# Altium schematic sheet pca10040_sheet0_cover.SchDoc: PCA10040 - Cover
size A3; Revision: 1.1.0; SheetNumber: 0; SheetTotal: 5; DrawnBy: KJP; ProjectNumber: 4397; DocumentSize: A3; PCBRevision: 0071KJP; PCAName: PCA10040; PCBNumber: 400150
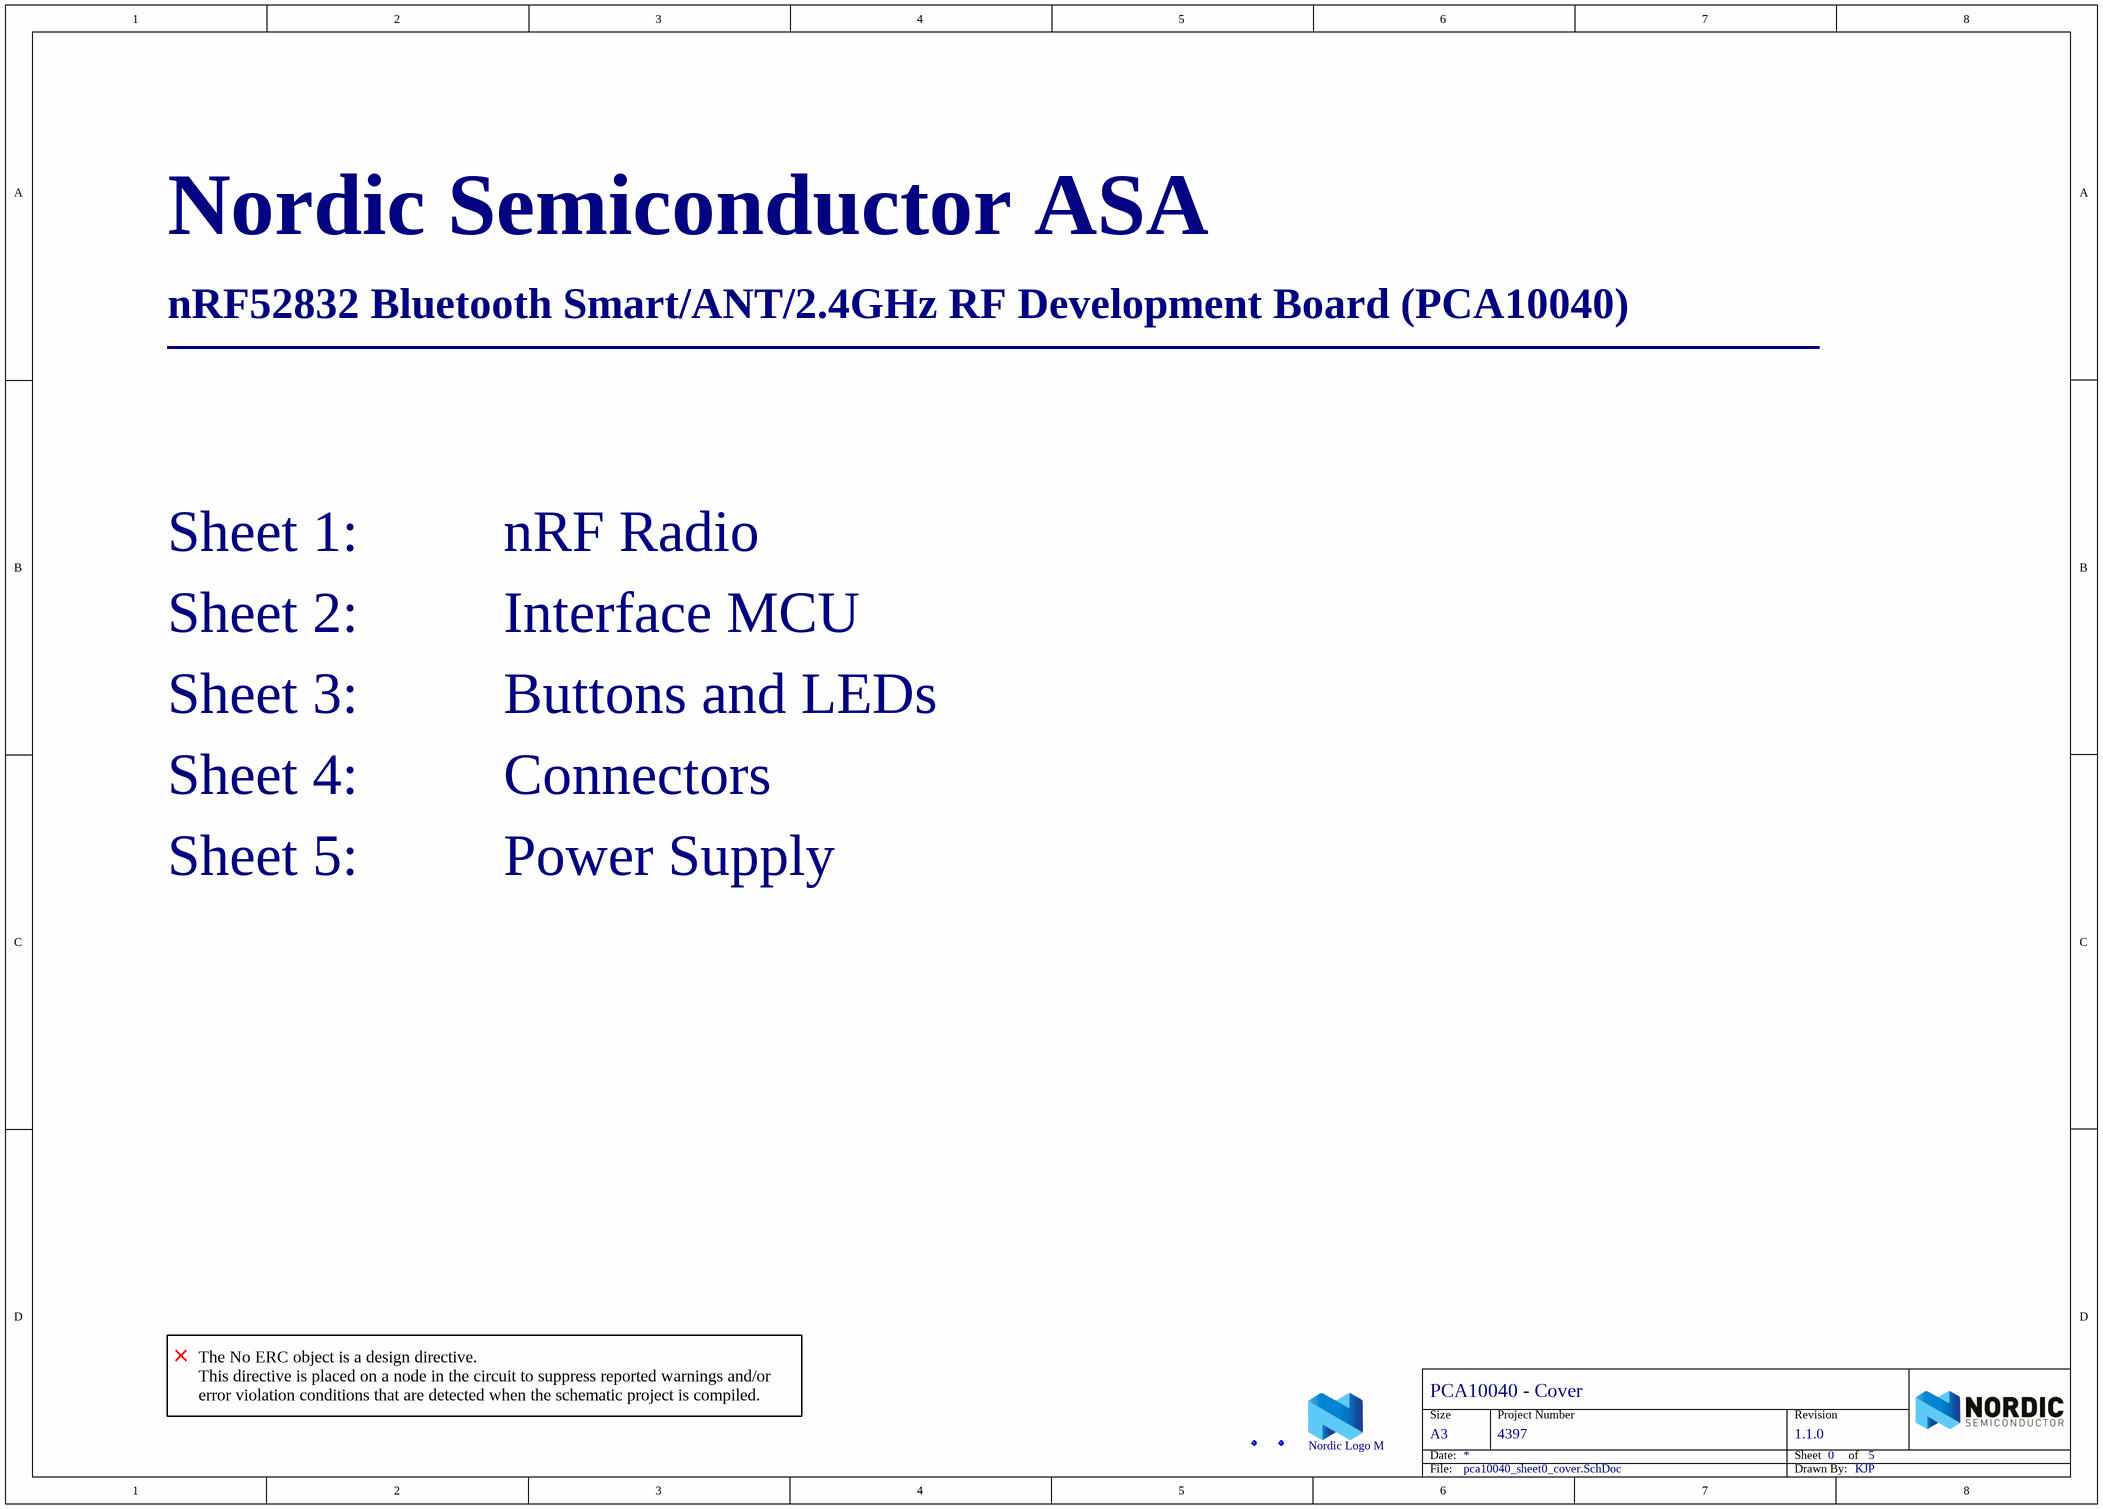
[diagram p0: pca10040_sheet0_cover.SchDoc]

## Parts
Fid1  Fiducial mark  [Fiducial]  (value not drawn)
Fid2  Fiducial mark  [Fiducial]  (value not drawn)
LOGO1  Nordic Logo M  [NORDIC_LOGO_M]  (no BOM)

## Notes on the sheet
- Nordic Semiconductor ASA
- nRF52832 Bluetooth Smart/ANT/2.4GHz RF Development Board (PCA10040)
- ________________________________________________________
- Sheet 1:          nRF Radio
- Sheet 2:          Interface MCU
- Sheet 3:          Buttons and LEDs
- Sheet 4:          Connectors
- Sheet 5:          Power Supply
- The No ERC object is a design directive.
  This directive is placed on a node in the circuit to suppress reported warnings and/or error violation conditions that are detected when the schematic project is compiled.

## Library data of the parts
Fid1 Fid2 = Fid-Mark: Artikkelnr Noca: N.A.
LOGO1 = Nordic Logo M: Nordic Logo, medium size; Artikkelnr Noca: N.A.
